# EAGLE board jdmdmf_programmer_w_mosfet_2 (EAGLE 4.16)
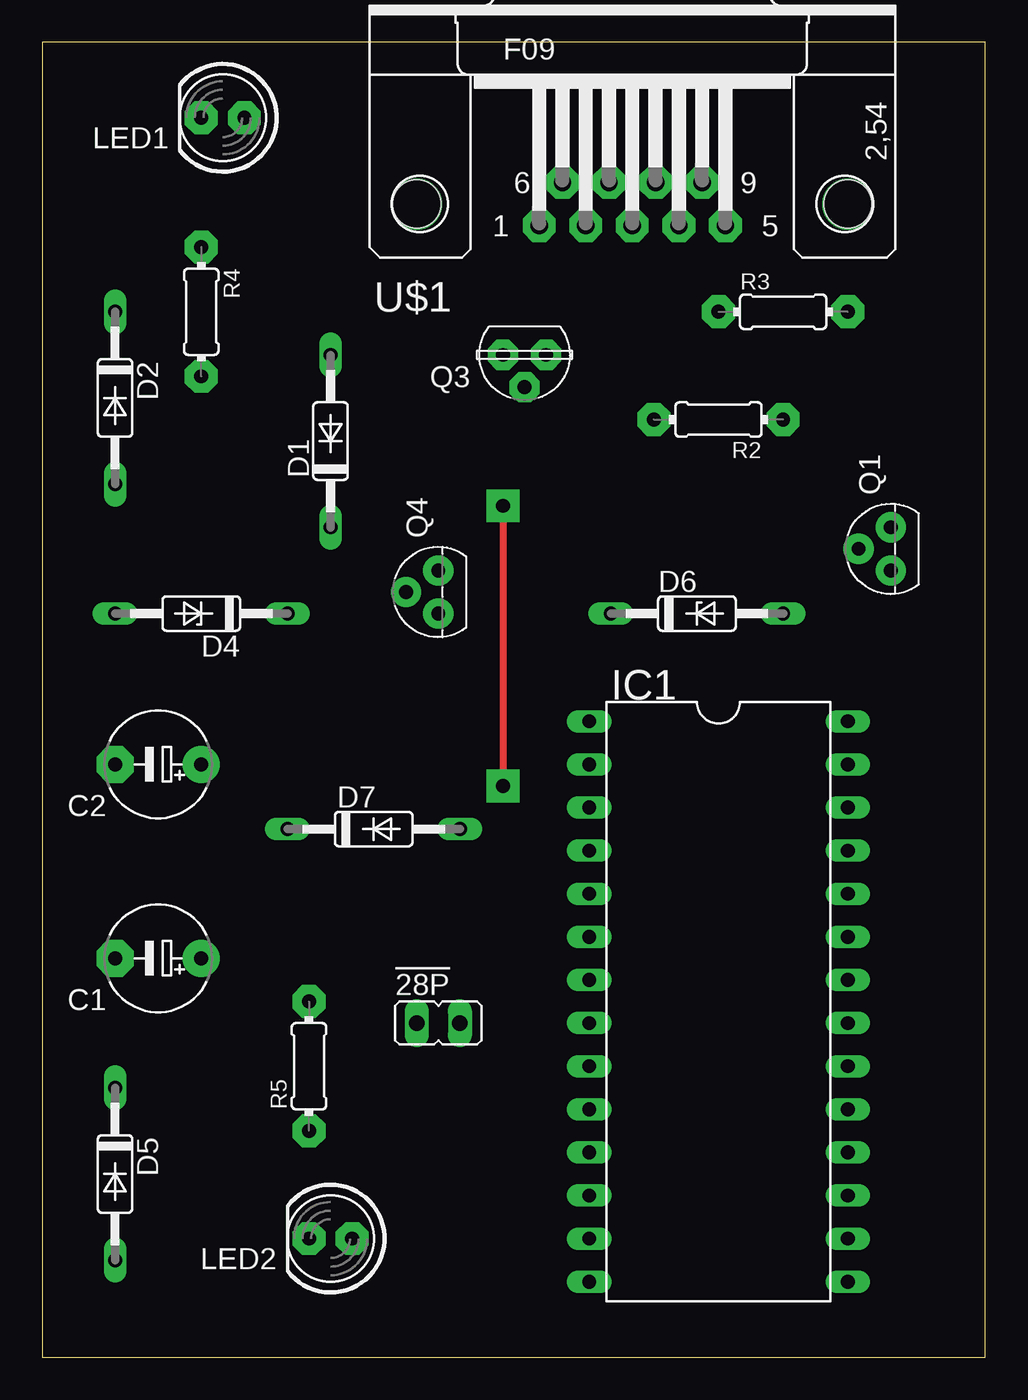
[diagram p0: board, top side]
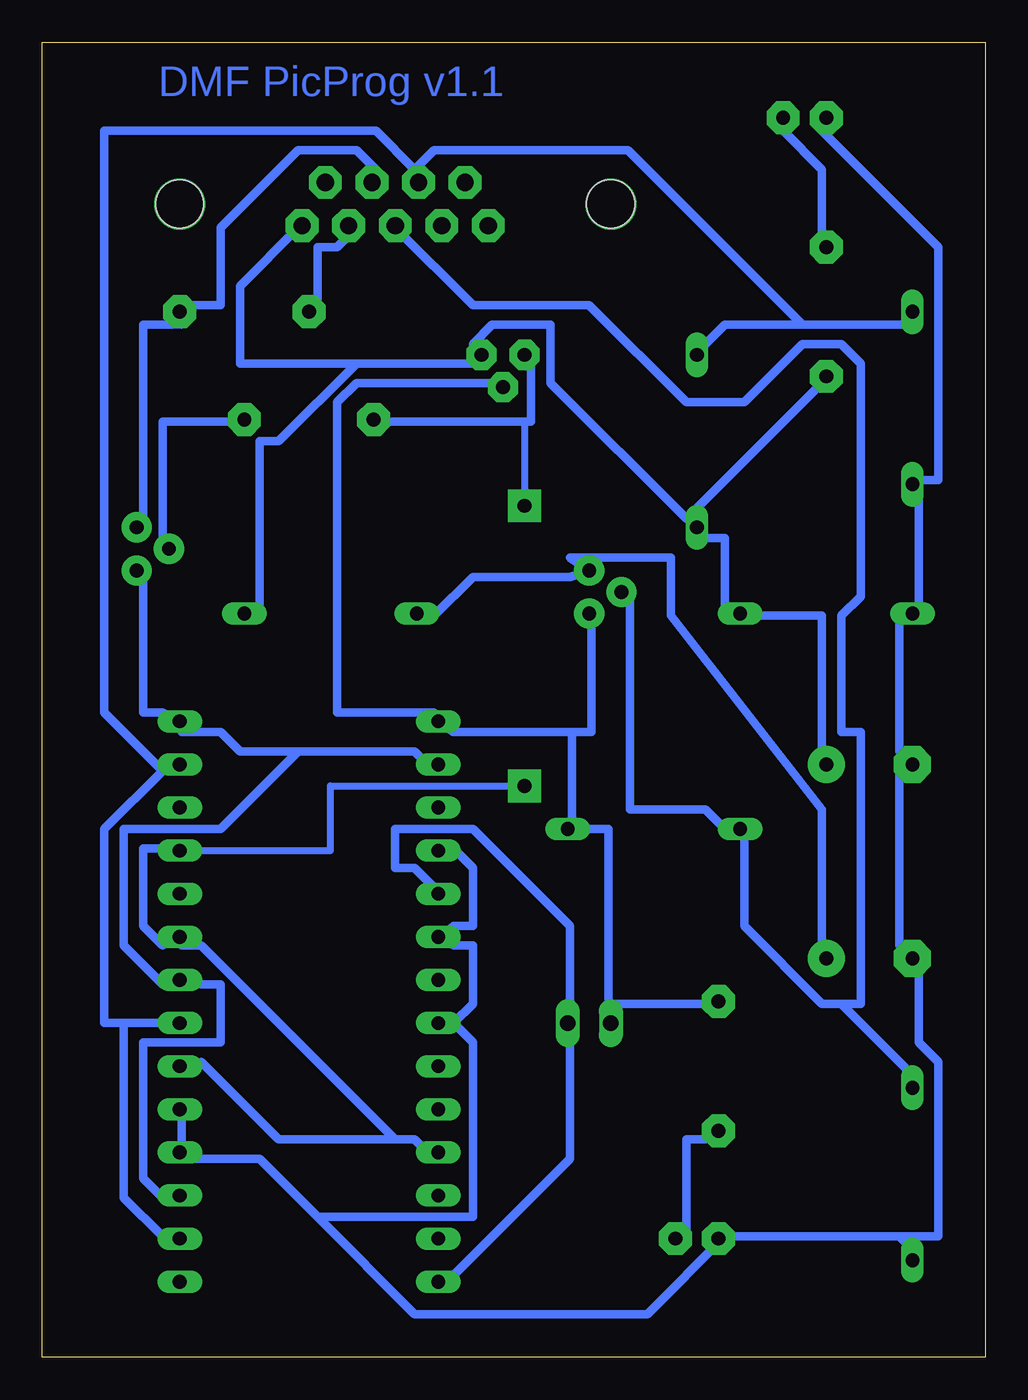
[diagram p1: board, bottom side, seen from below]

Size 55.55 x 77.46 mm. Coordinates in mm from the lower left corner, seen from the top.
Outline: 0,0 55.55,0 55.55,77.46 0,77.46 0,0
Copper layers (1*16): Top 0.035mm / dielectric 1.5mm / Bottom 0.035mm
Design rules "default": minimum track width 8mil, minimum drill 24mil, track to track 9mil, track to pad 9mil, pad to pad 8mil, via to via 8mil, smd to smd 8mil, copper to edge 40mil, drill to drill 8mil, minimum pad ring 10mil, minimum via ring 8mil, stop-mask expansion 4mil, vias tented up to drill 0mil, thermal gap 10mil
Net classes: 0 default: width 0.508 mm; 1 power: width 0.559 mm

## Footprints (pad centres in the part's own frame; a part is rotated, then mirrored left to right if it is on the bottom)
JP1 = drill 0.914 long: 1 0,-1.27; 2 0,1.27
CPOL-USE5-6 = drill 0.813 pad 2.184 round: + -2.54,0 | drill 0.813 pad 2.184 octagon: - 2.54,0
DIODE_DO35-10 = drill 0.813 long: A 5.08,0; C -5.08,0
DO35Z10 = drill 0.813 long: A 5.08,0; C -5.08,0
DIL28-6 = drill 0.813 long: 1 -16.51,-7.62; 2 -13.97,-7.62; 3 -11.43,-7.62; 4 -8.89,-7.62; 5 -6.35,-7.62; 6 -3.81,-7.62; 7 -1.27,-7.62; 8 1.27,-7.62; 9 3.81,-7.62; 10 6.35,-7.62; 11 8.89,-7.62; 12 11.43,-7.62; 13 13.97,-7.62; 14 16.51,-7.62; 15 16.51,7.62; 16 13.97,7.62; 17 11.43,7.62; 18 8.89,7.62; 19 6.35,7.62; 20 3.81,7.62; 21 1.27,7.62; 22 -1.27,7.62; 23 -3.81,7.62; 24 -6.35,7.62; 25 -8.89,7.62; 26 -11.43,7.62; 27 -13.97,7.62; 28 -16.51,7.62
LED5MM = drill 0.813 pad 1.93 octagon: A -1.27,0; K 1.27,0
NPN_TO92_BP = drill 0.813 pad 1.778 round: 1 1.27,0; 2 0,1.905; 3 -1.27,0
TO_237 = drill 0.813 pad 1.778 octagon: 1 1.27,-1.27; 2 0,0.635; 3 -1.27,-1.27
R_US_0204/7 = drill 0.813 pad 1.93 octagon: 1 -3.81,0; 2 3.81,0
SUBD_F9H = drill 1.016 pad 1.93 octagon: 1 -5.486,-7.62; 2 -2.743,-7.62; 3 0,-7.62; 4 2.743,-7.62; 5 5.486,-7.62; 6 -4.115,-5.08; 7 -1.372,-5.08; 8 1.372,-5.08; 9 4.115,-5.08 | hole 2.8: -12.7,-6.35; 12.7,-6.35

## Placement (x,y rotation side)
!28P  [JP1]  23.33,19.68 270 top
C1  100uF 40v  [CPOL-USE5-6]  6.82,23.49 180 top
C2  22uF 16v  [CPOL-USE5-6]  6.82,34.92 180 top
D1  1N4148  [DIODE_DO35-10]  16.98,53.97 90 top
D2  1N4148  [DIODE_DO35-10]  4.28,56.51 270 top
D4  5.1v  [DO35Z10]  9.36,43.81 180 top
D5  1N4148  [DIODE_DO35-10]  4.28,10.79 270 top
D6  8.2v  [DO35Z10]  38.57,43.81 0 top
D7  1N4148  [DIODE_DO35-10]  19.52,31.11 0 top
IC1  [DIL28-6]  39.84,20.95 270 top
LED1  Power  [LED5MM]  10.63,73.02 180 top
LED2  Vpp  [LED5MM]  16.98,6.98 180 top
Q1  2N3904  [NPN_TO92_BP]  50,47.62 90 top
Q3  2n7000  [TO_237]  28.41,57.78 180 top
Q4  2N3904  [NPN_TO92_BP]  23.33,45.08 90 top
R2  10k  [R_US_0204/7]  39.84,55.24 180 top
R3  1.5k  [R_US_0204/7]  43.65,61.59 0 top
R4  1.2k  [R_US_0204/7]  9.36,61.59 270 top
R5  4.7k  [R_US_0204/7]  15.71,17.14 90 top
U$1  SUBD_F9H_JDM  [SUBD_F9H]  34.76,74.29 0 top

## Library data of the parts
!28P = jumper
C1 C2 D1 D2 D5 D7 LED1 LED2 Q1 Q3 Q4 R2-R5 U$1 = 1dmf
D4 D6 = diode
IC1 = ic-package

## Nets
2N3904: C1.+ D6.C Q4.1
CLK: D1.A D2.C IC1.16 IC1.21 IC1.27 U$1.7
DATA: IC1.2 IC1.17 IC1.22 IC1.28 Q1.3
N$1: Q1.2 R2.1
N$2: LED1.A R4.1
N$3: LED2.A R5.1
N$4: R3.1 U$1.4
N$5: Q1.1 R3.2 U$1.8
N$6: D5.C D7.C Q4.2 U$1.3
N$7: !28P.2 IC1.5 IC1.14
Q3: C2.+ D1.C D4.C D6.A Q3.3 R4.2 U$1.5
VDD: IC1.11 IC1.20 IC1.23 IC1.25 Q3.1 R2.2
VPP: !28P.1 D7.A IC1.1 Q3.2 Q4.3 R5.2
VSS: C1.- C2.- D2.A D4.A D5.A IC1.4 IC1.6 IC1.8 IC1.18 IC1.19 LED1.K LED2.K

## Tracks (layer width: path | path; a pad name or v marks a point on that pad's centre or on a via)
2N3904
  Bottom 0.508: D6.C 32.47,43.68 30.19,45.97 24.47,45.97 Q4.1 24.47,47.11 18.5,47.11 18.5,43.68 9.61,32.25 9.61,24.25 C1.+
CLK
  Bottom 0.508: 50.76,19.68 50.76,9.39 48.48,7.11 IC1.16 | 50.76,19.68 IC1.21 | 48.48,34.54 51.91,31.11 51.91,19.68 50.76,19.68 | 10.76,60.83 3.9,60.83 D2.C | 10.76,60.83 15.33,60.83 16.47,59.69 D1.A | 33.62,69.97 32.47,71.11 21.04,71.11 10.76,60.83 | 48.48,34.54 51.91,37.97 51.91,72.26 35.9,72.26 33.62,69.97 | 48.48,34.54 IC1.27 | 33.62,69.97 U$1.7
DATA
  Bottom 0.508: IC1.17 48.48,9.39 49.62,10.54 49.62,18.54 45.05,18.54 45.05,21.97 46.19,21.97 IC1.22 48.48,21.97 50.76,24.25 50.76,31.11 45.05,31.11 40.47,35.68 | 40.47,35.68 43.9,35.68 45.05,36.83 47.33,36.83 IC1.28 48.48,37.97 49.62,37.97 49.62,45.97 Q1.3 | 40.47,35.68 33.62,35.68 32.47,34.54 IC1.2
N$1
  Bottom 0.508: Q1.2 48.48,48.26 48.48,55.11 43.9,55.11 R2.1
N$2
  Bottom 0.508: R4.1 9.61,65.4 9.61,69.97 11.9,72.26 LED1.A
N$3
  Bottom 0.508: LED2.A 17.62,7.11 17.62,12.82 16.47,12.82 R5.1
N$4
  Bottom 0.508: R3.1 39.33,61.97 39.33,65.4 38.19,65.4 37.05,66.54 U$1.4
N$5
  Bottom 0.508: Q1.1 49.62,49.4 49.62,60.83 47.33,60.83 R3.2 47.33,61.97 45.05,61.97 45.05,66.54 40.47,71.11 37.05,71.11 35.9,69.97 U$1.8
N$6
  Bottom 0.508: 8.47,20.82 3.9,16.25 D5.C | 8.47,20.82 9.61,20.82 14.19,25.39 14.19,31.11 D7.C 15.33,31.11 16.47,32.25 20.92,32.25 20.92,44.83 Q4.2 | 8.47,20.82 7.33,20.82 7.33,36.83 8.47,36.83 8.47,43.68 7.33,44.83 7.33,58.54 8.47,59.69 10.76,59.69 14.19,56.26 17.62,56.26 23.33,61.97 30.19,61.97 34.76,66.54 U$1.3
N$7
  Bottom 0.508: IC1.14 31.33,4.82 24.47,11.68 24.47,18.54 !28P.2 24.47,20.82 24.47,25.39 30.19,31.11 34.76,31.11 34.76,28.82 33.62,28.82 32.47,27.68 IC1.5
Q3
  Bottom 0.508: 17.62,49.4 9.61,57.4 R4.2 | C2.+ 9.61,35.68 9.61,43.68 14.19,43.68 D4.C 15.33,43.68 15.33,48.26 16.47,48.26 D1.C 17.62,49.4 | 37.05,58.54 41.62,53.97 42.76,53.97 42.76,43.68 D6.A | 37.05,58.54 30.19,58.54 Q3.3 30.19,59.69 29.05,60.83 25.62,60.83 25.62,57.4 17.62,49.4 | 37.05,58.54 43.9,58.54 43.9,63.11 40.47,66.54 U$1.5
S$1  (via drill 2)
  other vias: 22.06,67.94
S$2  (via drill 2)
  other vias: 47.46,67.94
VDD  (via drill 0.8 pad 1.93)
  Top 0.406: v27.14,50.16 v27.14,33.65
  Bottom 0.406: IC1.25 38.57,29.84 38.57,33.65 v27.14,33.65 | 26.76,55.11 27.14,55.11 v27.14,50.16
  Bottom 0.508: Q3.1 26.76,58.54 26.76,55.11 35.9,55.11 R2.2 | IC1.25 48.48,29.97 49.62,29.97 49.62,25.39 48.48,24.25 IC1.23 47.33,24.25 46.19,24.25 34.76,12.82 | 34.76,12.82 41.62,12.82 46.19,17.39 IC1.20 | 34.76,12.82 33.62,12.82 32.47,11.68 IC1.11
VPP
  Bottom 0.508: 22.19,20.82 16.47,20.82 R5.2 | 24.35,31.11 24.35,36.83 | 24.35,36.83 31.33,36.83 IC1.1 32.47,37.97 38.19,37.97 38.19,56.26 37.05,57.4 29.05,57.4 Q3.2 | 24.35,36.83 23.2,36.83 23.2,43.68 Q4.3 | 22.19,20.82 22.19,31.11 24.35,31.11 | 22.19,20.82 !28P.1 | 24.35,31.11 D7.A
VSS
  Bottom 0.508: LED1.K 9.61,72.26 2.76,65.4 2.76,51.68 3.9,51.68 D2.A 3.9,50.54 3.9,43.68 D4.A 5.04,43.68 5.04,35.68 C2.- 5.04,34.54 5.04,24.25 C1.- 3.9,23.11 3.9,18.54 2.76,17.39 2.76,7.11 5.04,7.11 | 31.33,19.68 30.19,20.82 30.19,24.25 31.33,24.25 IC1.6 31.33,25.39 30.19,25.39 30.19,28.82 31.33,29.97 IC1.4 | 47.33,11.68 47.33,13.96 IC1.19 | 5.04,7.11 3.9,5.96 D5.A | 5.04,7.11 15.33,7.11 | 47.33,11.68 42.76,11.68 39.33,8.25 | 39.33,8.25 33.62,2.53 19.9,2.53 15.33,7.11 | 47.33,11.68 IC1.18 | 15.33,7.11 LED2.K | 31.33,19.68 30.19,18.54 30.19,8.25 39.33,8.25 | 31.33,19.68 IC1.8

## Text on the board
Bottom: DMF PicProg v1.1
